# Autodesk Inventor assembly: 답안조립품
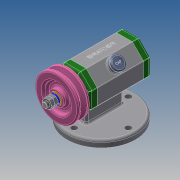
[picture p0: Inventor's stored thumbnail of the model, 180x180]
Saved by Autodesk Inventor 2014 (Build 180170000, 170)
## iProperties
Created: 2021-02
Part Number: 답안조립품
Document SubType Name: Weldment
Designer: kb542-17
Weld Material: Welded Aluminum-6061
Author: kb542-17
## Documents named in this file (14)
- C:\Users\kb542-17\Desktop\710204V1023\답안조립품.iam
- C:\Users\kb542-17\Desktop\710204V1023\본체.ipt
- C:\Users\kb542-17\Desktop\710204V1023\V벨트풀리.ipt
- C:\Users\kb542-17\Desktop\710204V1023\고무캡.ipt
- C:\Users\kb542-17\Desktop\710204V1023\너트 M8.ipt
- C:\Users\kb542-17\Desktop\710204V1023\뒤커버.ipt
- C:\Users\kb542-17\Desktop\710204V1023\베어링 15 x 32 x 9.ipt
- C:\Users\kb542-17\Desktop\710204V1023\볼트 M4 x 12.ipt
- C:\Users\kb542-17\Desktop\710204V1023\스프링와셔 8.ipt
- C:\Users\kb542-17\Desktop\710204V1023\앞커버.ipt
- C:\Users\kb542-17\Desktop\710204V1023\오일 실 15 25 7.ipt
- C:\Users\kb542-17\Desktop\710204V1023\와셔 8x17.ipt
- C:\Users\kb542-17\Desktop\710204V1023\축.ipt
- C:\Users\kb542-17\Desktop\710204V1023\키 3 x 3 x 12.ipt
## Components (2 placed, 2 different names)
1. V벨트풀리:1
2. 고무캡:1 — 각도:1
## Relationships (1: Angle 1)
- 각도:1 [Angle]: 고무캡:1
